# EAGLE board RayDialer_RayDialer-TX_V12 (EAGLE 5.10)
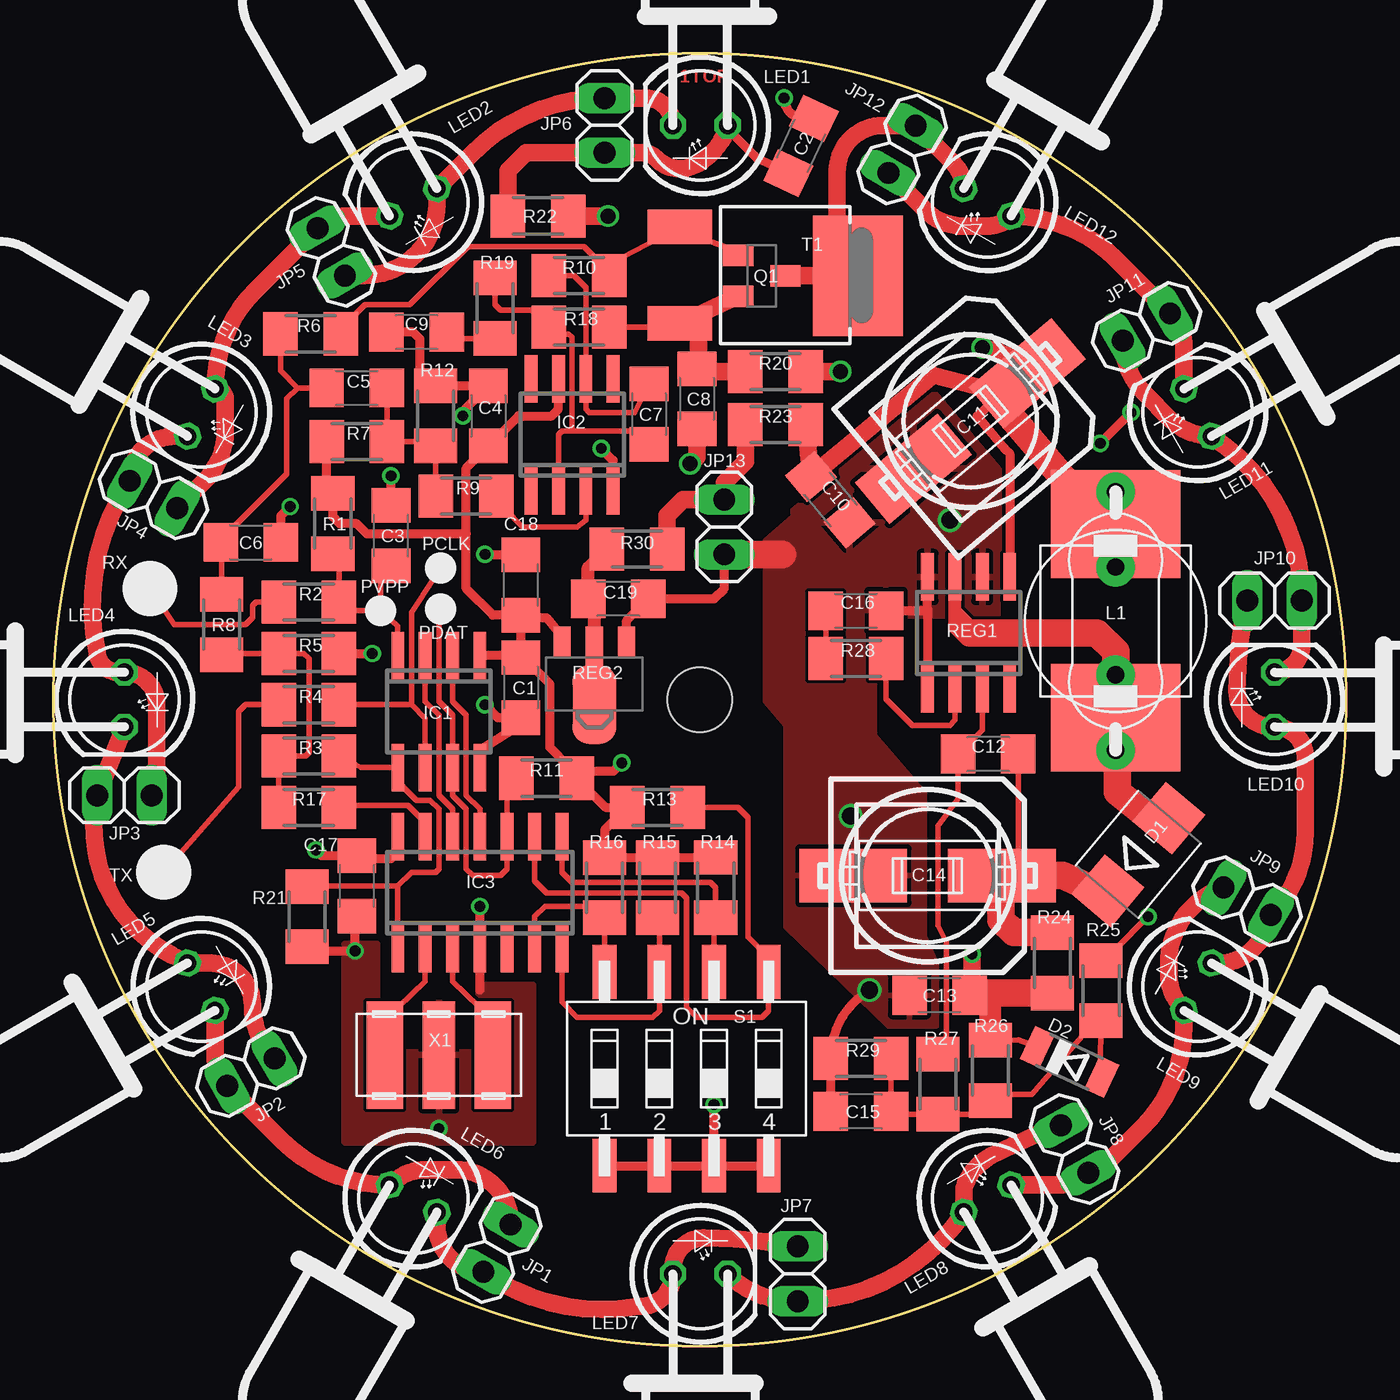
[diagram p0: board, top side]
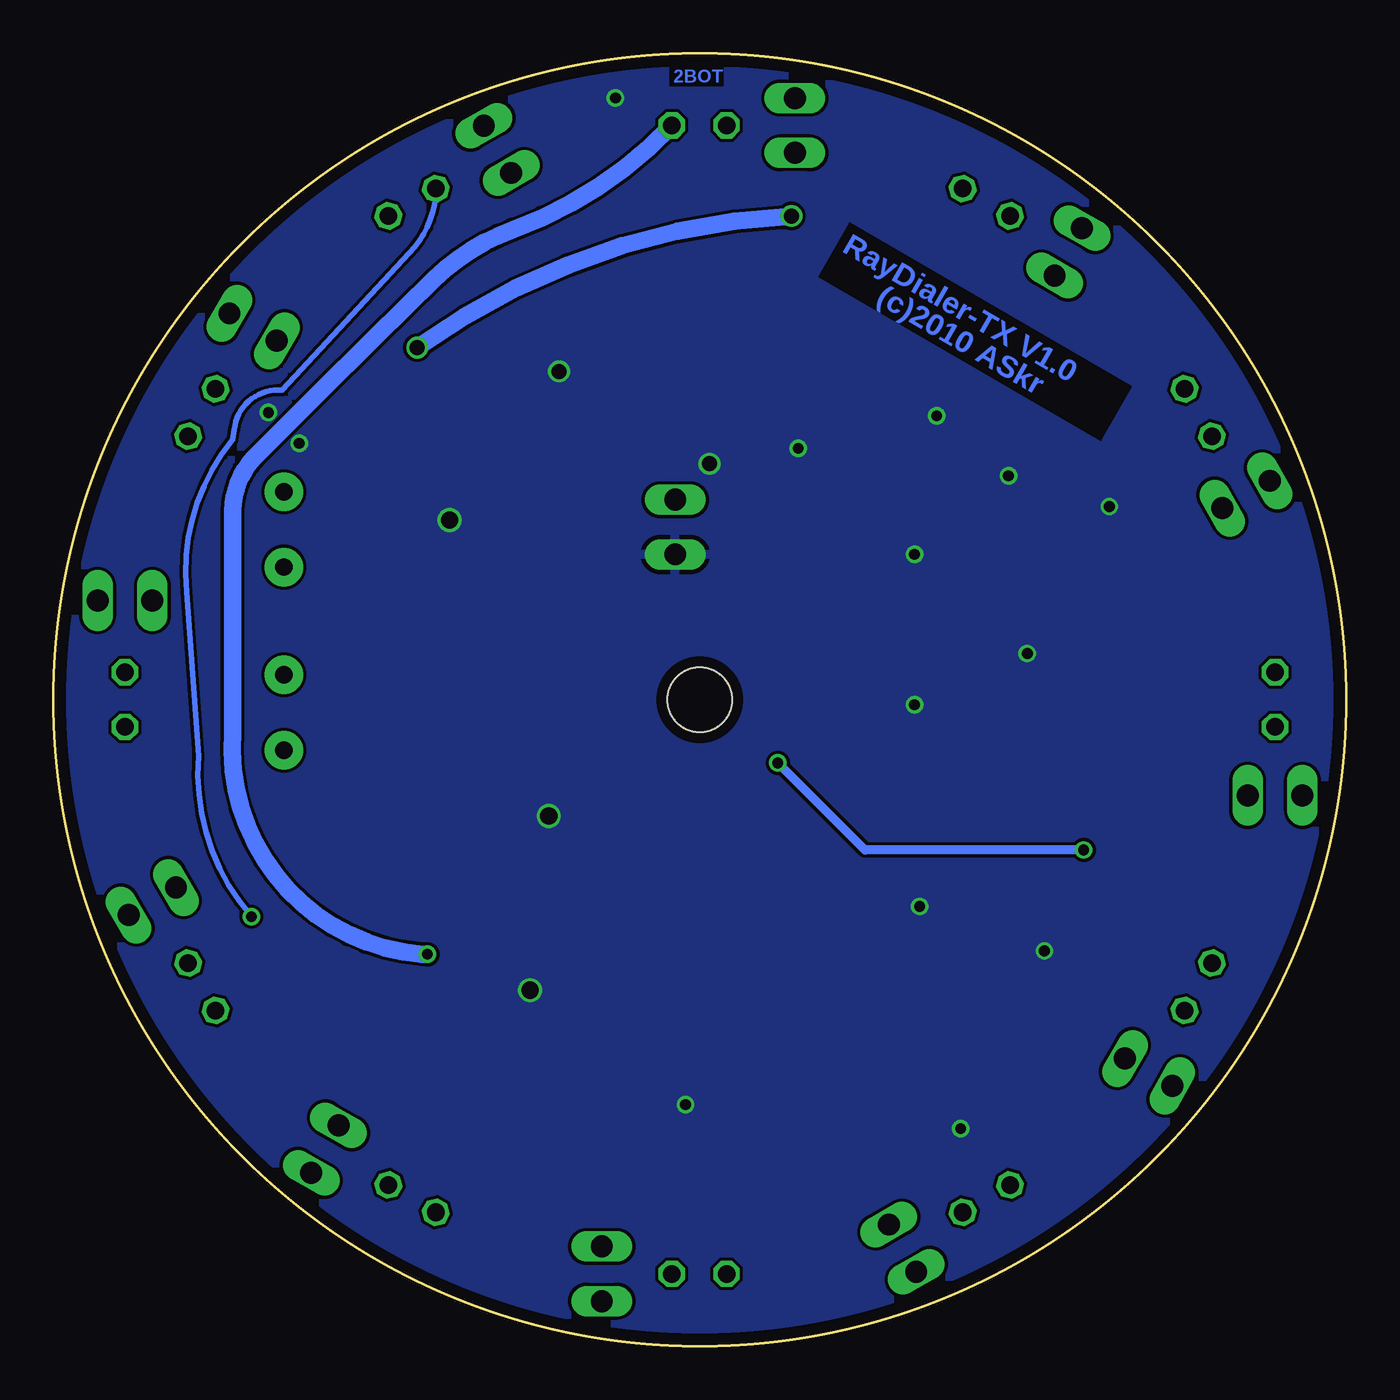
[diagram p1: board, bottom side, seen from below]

Size 60 x 60 mm. Coordinates in mm from the lower left corner, seen from the top.
Outline: circle at 30,30 radius 30
Copper layers (1*16): Top 0.035mm / dielectric 1.5mm / Bottom 0.035mm
Design rules "pcb-pool-2009": minimum track width 6mil, minimum drill 12mil, track to track 6mil, track to pad 6mil, pad to pad 6mil, via to via 6mil, smd to smd 6mil, copper to edge 20mil, drill to drill 8mil, minimum pad ring 8mil, minimum via ring 6mil, stop-mask expansion 3mil, vias tented up to drill 0mil, thermal gap 8mil
Holes 3 mm at 30,30
tRestrict: 6 lines
bRestrict: 8 lines

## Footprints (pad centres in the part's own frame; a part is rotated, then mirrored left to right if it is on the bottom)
C1206 = smd 1.6 x 1.8: 1 -1.4,0; 2 1.4,0
AKKI_CAP_MULTI2 = smd 5 x 2.5: + 3.45,0; - -3.45,0
AKKI_DIODE_SMB = smd 2.4 x 2.4: A 2.2,0; C -2.2,0
SOD80-R = smd 1 x 1.7: A 1.65,0; C -1.65,0
SOIC8 = smd 0.6 x 2.2: 1 -1.905,-2.6; 2 -0.635,-2.6; 3 0.635,-2.6; 4 1.905,-2.6; 5 1.905,2.6; 6 0.635,2.6; 7 -0.635,2.6; 8 -1.905,2.6
SO08 = smd 0.6 x 2.2: 1 -1.905,-2.6; 2 -0.635,-2.6; 3 0.635,-2.6; 4 1.905,-2.6; 5 1.905,2.6; 6 0.635,2.6; 7 -0.635,2.6; 8 -1.905,2.6
AKKI_SO-14 = smd 0.6 x 2.2: 1 -3.81,-2.6; 2 -2.54,-2.6; 3 -1.27,-2.6; 4 0,-2.6; 5 1.27,-2.6; 6 2.54,-2.6; 7 3.81,-2.6; 8 3.81,2.6; 9 2.54,2.6; 10 1.27,2.6; 11 0,2.6; 12 -1.27,2.6; 13 -2.54,2.6; 14 -3.81,2.6
1X02 = drill 1.016 long: 1 -1.27,0; 2 1.27,0
AKKI_MULTICOIL = drill 0.8 pad 1.778 round: 1@1 -6,0; 1@2 -2.5,0; 2@1 2.5,0; 2@2 6,0 | smd 5 x 6: 1@3 -4.5,0; 2@3 4.5,0
AKKI_LED5MM = drill 0.813 octagon: A -1.27,0; K 1.27,0
TP14R = smd 1.4 x 1.4: TP 0,0
SOT23-BEC = smd 1 x 1.4: B -0.95,-1.1; C 0,1.1; E 0.95,-1.1
M1206 = smd 1.6 x 2: 1 -1.4,0; 2 1.4,0
AKKI_SOIC8 = smd 0.6 x 2.2: 1 -1.905,-2.6; 2 -0.635,-2.6; 3 0.635,-2.6; 4 1.905,-2.6; 5 1.905,2.6; 6 0.635,2.6; 7 -0.635,2.6; 8 -1.905,2.6
SOT89 = smd 0.8 x 1.4: 1 -1.499,-1.981; 3 1.499,-1.981 | smd 0.8 x 1.9: 2 0,-1.727 | smd 2.032 x 3.65: 2@1 0,0.94
B2,54 = smd 2.54 x 2.54: TP 0,0
AKKI_SW04-SMD = smd 1.1 x 2.5: 1 -3.81,-4.5; 2 -1.27,-4.5; 3 1.27,-4.5; 4 3.81,-4.5; 5 3.81,4.5; 6 1.27,4.5; 7 -1.27,4.5; 8 -3.81,4.5
AKKI_DPAK = smd 1.6 x 2.997: 1 -2.261,-4.928; 3 2.21,-4.928 | smd 5.588 x 4.191: 4 0,3.353
AKKI_RESO3SMD = smd 1.7 x 5: 1 -2.5,0; 3 2.5,0 | smd 1.5 x 5: 2 0,0

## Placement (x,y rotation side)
C1  100n  [C1206]  21.69,30.56 270 top
C2  100n  [C1206]  34.71,55.72 65 top
C3  180p  [C1206]  15.66,37.63 90 top
C4  1u  [C1206]  20.18,43.18 270 top
C5  3n3  [C1206]  14.07,44.48 0 top
C6  330p  [C1206]  9.15,37.31 0 top
C7  180p  [C1206]  27.65,43.26 270 top
C8  33p  [C1206]  29.87,43.98 270 top
C9  10n  [C1206]  16.85,47.07 180 top
C10  100n  [C1206]  36.06,39.29 310 top
C11  150u;10V  [AKKI_CAP_MULTI2]  42.57,42.94 40 top
C12  n.p.  [C1206]  43.39,27.48 180 top
C13  1u;35V  [C1206]  41.14,16.27 180 top
C14  100u;35V  [AKKI_CAP_MULTI2]  40.58,21.83 0 top
C15  220n  [C1206]  37.49,10.88 180 top
C16  10u  [C1206]  37.25,34.13 0 top
C17  100n  [C1206]  14.07,21.35 270 top
C18  100n  [C1206]  21.69,35.32 90 top
C19  1u  [C1206]  26.22,34.69 180 top
D1  MBRS130  [AKKI_DIODE_SMB]  50.37,22.81 50 top
D2  30V  [SOD80-R]  47.17,13.18 335 top
IC1  PIC12F683  [SOIC8]  17.88,29.45 180 top
IC2  MCP601SN  [SO08]  24.07,42.31 0 top
IC3  HT9200  [AKKI_SO-14]  19.79,21.04 0 top
JP1  [1X02]  20.58,4.53 60 top
JP2  [1X02]  9.15,12.7 30 top
JP3  [1X02]  3.28,25.56 0 top
JP4  [1X02]  4.63,39.53 330 top
JP5  [1X02]  12.88,50.8 300 top
JP6  [1X02]  25.58,56.68 270 top
JP7  [1X02]  34.55,3.34 90 top
JP8  [1X02]  47.41,9.13 120 top
JP9  [1X02]  55.43,20.64 150 top
JP10  [1X02]  56.7,34.61 180 top
JP11  [1X02]  50.74,47.31 210 top
JP12  [1X02]  39.39,55.57 240 top
JP13  [1X02]  31.14,38.02 90 top
L1  100u  [AKKI_MULTICOIL]  49.31,33.66 270 top
LED1  [AKKI_LED5MM]  30.03,56.68 180 top
LED2  [AKKI_LED5MM]  16.69,53.1 210 top
LED3  [AKKI_LED5MM]  6.85,43.34 240 top
LED4  [AKKI_LED5MM]  3.28,30.01 270 top
LED5  [AKKI_LED5MM]  6.85,16.67 300 top
LED6  [AKKI_LED5MM]  16.69,6.83 330 top
LED7  [AKKI_LED5MM]  30.03,3.34 0 top
LED8  [AKKI_LED5MM]  43.36,6.83 30 top
LED9  [AKKI_LED5MM]  53.12,16.67 60 top
LED10  [AKKI_LED5MM]  56.7,30.01 90 top
LED11  [AKKI_LED5MM]  53.12,43.34 120 top
LED12  [AKKI_LED5MM]  43.36,53.1 150 top
PCLK  [TP14R]  17.96,36.12 0 top
PDAT  [TP14R]  17.96,34.21 0 top
PVPP  [TP14R]  15.18,34.13 0 top
Q1  BC817-40  [SOT23-BEC]  32.88,49.69 270 top
R1  100k  [M1206]  12.96,38.18 90 top
R2  1k  [M1206]  11.85,34.53 180 top
R3  100k  [M1206]  11.85,27.39 0 top
R4  1k  [M1206]  11.85,29.77 180 top
R5  47k  [M1206]  11.85,32.15 180 top
R6  n.p.  [M1206]  11.93,46.99 0 top
R7  470k  [M1206]  14.07,41.99 180 top
R8  100k  [M1206]  7.8,33.5 270 top
R9  47k  [M1206]  19.15,39.45 180 top
R10  1k  [M1206]  24.39,49.69 180 top
R11  100k  [M1206]  22.88,26.36 0 top
R12  82k  [M1206]  17.72,43.18 270 top
R13  100k  [M1206]  28.04,25.01 180 top
R14  100k  [M1206]  30.74,21.28 90 top
R15  100k  [M1206]  28.04,21.28 90 top
R16  100k  [M1206]  25.58,21.28 90 top
R17  0E  [M1206]  11.85,25.01 180 top
R18  100k  [M1206]  24.39,47.31 0 top
R19  100k  [M1206]  20.5,48.18 90 top
R20  10E  [M1206]  33.52,45.25 0 top
R21  100k  [M1206]  11.77,19.93 90 top
R22  0E; n.p.  [M1206]  22.49,52.47 180 top
R23  0E  [M1206]  33.52,42.79 0 top
R24  3E3  [M1206]  46.38,17.78 270 top
R25  82k  [M1206]  48.64,16.49 90 top
R26  n.p.  [M1206]  43.49,12.79 90 top
R27  1k  [M1206]  41.06,12.15 270 top
R28  4k7  [M1206]  37.25,31.91 0 top
R29  82k  [M1206]  37.49,13.34 0 top
R30  3E3  [M1206]  27.09,36.99 180 top
REG1  LT1172CS8  [AKKI_SOIC8]  42.49,33.1 0 top
REG2  S817A33  [SOT89]  25.11,30.72 180 top
RX  [B2,54]  4.47,35.17 0 top
S1  SW04-SMD  [AKKI_SW04-SMD]  29.39,12.86 0 top
T1  ZXT1053AK  [AKKI_DPAK]  34,49.69 270 top
TX  [B2,54]  5.1,21.99 0 top
X1  3.58MHz  [AKKI_RESO3SMD]  17.88,13.5 0 top

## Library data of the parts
C1-C3 C5-C10 C12 C15 C17 C18 R1-R30 = rcl
C4 C13 C16 C19 = rcl; TYPE: cer.
C11 C14 D1 D2 IC1 IC3 L1 LED1-LED12 REG1 REG2 S1 T1 X1 = Akki
IC2 = linear
JP1-JP13 = pinhead
PCLK PDAT PVPP RX TX = testpad
Q1 = transistor-npn

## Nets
+3V3: C1.1 C4.2 C17.1 C18.1 IC1.1 IC2.7 IC3.14 R1.2 R7.2 R11.2 R13.2 R14.2 R15.2 R16.2 REG2.3
+UB: JP13.2 R23.1 R30.1
GND: C1.2 C2.2 C3.2 C4.1 C6.2 C8.2 C9.2 C10.2 C11.- C13.2 C14.- C15.2 C16.2 C17.2 C18.2 C19.1 IC1.8 IC2.4 IC3.4 JP13.1 R5.1 R12.1 R20.2 R21.1 R29.1 REG1.1 REG1.6 REG1.8 REG2.1 S1.1 S1.2 S1.3 S1.4 X1.2
HT_CLK: IC1.2 IC3.11
HT_CS: IC1.5 IC3.1 R3.2 R21.2
HT_DAT: IC1.3 IC3.12
HT_SP: IC1.7 IC3.10 PDAT.TP R11.1
N$1: IC3.6 R16.1 S1.8
N$2: IC3.7 R15.1 S1.7
N$3: IC3.8 R14.1 S1.6
N$4: IC3.9 R13.1 S1.5
N$5: IC3.3 X1.3
N$6: IC3.2 X1.1
N$7: C5.2 R7.1 R9.2 R12.2
N$8: C15.1 D2.A R25.1 R26.1 R27.2 R29.2
N$9: IC2.3 R9.1
N$10: C7.1 IC2.6 R10.2
N$11: C5.1 C6.1 R6.1 R8.1
N$12: C8.1 Q1.E R18.2 R20.1 T1.3
N$13: C7.2 IC2.2 R18.1 R19.2
N$14: C9.1 R19.1
N$15: JP12.1 LED12.K Q1.C R25.2 T1.4
N$16: Q1.B R6.2 R10.1 T1.1
N$17: C19.2 R30.2 REG2.2
N$18: R3.1 R5.2 R8.2 R17.2
N$19: C10.1 C11.+ L1.1@1 R22.1 R23.2 REG1.5
N$20: R4.2 TX.TP
N$21: D1.A L1.2@2 REG1.7
N$22: IC3.13 R17.1
N$24: C12.1 C14.+ D1.C R24.1
N$25: R2.2 RX.TP
N$26: C16.1 R28.1
N$27: R28.2 REG1.2
N$28: C12.2 R27.1 REG1.3
N$29: JP5.2 JP6.1 LED1.K LED2.A
N$30: JP4.2 JP5.1 LED2.K LED3.A
N$31: JP3.2 JP4.1 LED3.K LED4.A
N$32: JP2.2 JP3.1 LED4.K LED5.A
N$33: JP1.2 JP2.1 LED5.K LED6.A
N$34: JP1.1 JP7.2 LED6.K LED7.A
N$35: JP7.1 JP8.2 LED7.K LED8.A
N$36: JP8.1 JP9.2 LED8.K LED9.A
N$37: JP9.1 JP10.2 LED9.K LED10.A
N$38: JP10.1 JP11.2 LED10.K LED11.A
N$39: JP11.1 JP12.2 LED11.K LED12.A
RX: C3.1 IC1.4 PVPP.TP R1.1 R2.1
TX: IC1.6 PCLK.TP R4.1
V+: C2.1 C13.1 D2.C JP6.2 LED1.A R22.2 R24.2 R26.2

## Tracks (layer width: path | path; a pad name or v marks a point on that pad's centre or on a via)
+3V3  (via drill 0.5)
  Top 0.406: IC1.1 21.44,32.05 C1.1 | IC3.14 15.98,22.94 15.66,22.62 14.2,22.62 C17.1 12.43,22.75 v12.17,23.02 | REG2.3 23.61,32.93 22.88,33.82 21.8,33.82 C18.1 | R15.2 R14.2 | R15.2 | R15.2 R16.2 25.58,23.95 R13.2 25.63,25.01 R11.2 | C1.1 21.8,31.96 23.04,30.72 23.04,27.78 23.91,26.91 23.91,26.72 R11.2 | IC2.7 23.44,43.5 23.12,43.18 21.58,43.18 C4.2 19.15,40.75 19.15,37.71 | C1.1 C18.1 | C1.1 | C18.1 20.39,33.92 19.15,35.17 19.15,37.71 | R7.2 12.67,39.87 R1.2 12.96,38.5 13.28,38.18 14.07,38.18 14.55,37.71 19.15,37.71 | v26.38,27.07 25.98,26.67 24.6,26.67 R11.2
  Bottom 0.406: v12.17,23.02 22.33,23.02 v26.38,27.07
+UB
  Top 0.813: R30.1 28.49,38.55 29.23,39.29 JP13.2 31.14,40.09 32.12,41.07 R23.1
GND  (via drill 0.5, 0.7, 0.8)
  Top 0.406: 40.58,34.21 REG1.1 | 40.58,34.21 REG1.8 | C16.2 40.5,34.13 40.58,34.21 | C17.2 13.99,19.88 v13.99,18.34 11.96,18.34 R21.1 | IC3.4 v19.79,20.4 | IC3.4 | IC3.4 19.79,16.51 | S1.1 S1.2 S1.3 | S1.3 S1.4 | S1.3 v30.66,11.19 | v30.66,11.19 | C19.1 30.66,34.69 31.14,35.17 JP13.1 | REG2.1 26.6,33.68 C19.1 | v20.03,29.77 20.63,29.16 C1.2 21.61,28.82 19.87,27.7 IC1.8 | C9.2 16.69,47.07 17.01,46.75 17.01,45.3 R12.1 C4.1 18.99,43.39 v18.99,43.18 | C6.2 10.55,38.55 v10.98,38.98 | R5.1 v14.79,32.15 | R5.1 | C18.2 20.05,36.72 v20.03,36.75 | C19.1 27.09,35.22 | C3.2 v15.66,40.4 | IC2.4 25.98,41.12 v25.42,41.67 | C15.2 R29.1 arc-59 v37.88,16.51 | C2.2 34.87,56.99 arc-90 v33.92,57.95 | v48.6,41.91 v50.03,43.34
  Top 0.813: R20.2 v36.54,45.25 | C8.2 29.87,41.28 v29.55,40.96
  Top 1.27: JP13.1 33.84,36.75
  other vias: 41.62,38.34 37.01,24.61 17.88,10.08
  pour Bottom: -1.56,61.52 61.3,61.52 61.3,-1.35 -1.56,-1.35
  pour Top: 34.31,38.74 40.9,44.21 43.92,40.64 43.92,34.05 39.87,34.05 39.87,36.36 36.3,36.36
  pour Top: 40.98,14.85 38.76,14.85 34,19.45 34,28.82 33.04,29.93 33.04,37.39 36.69,40.56 39.55,37.23 44.16,37.23 44.16,33.9 39.71,33.9 39.71,35.32 38.12,35.32 38.12,28.34 40.42,25.64 40.42,18.97 40.98,17.7
  pour Top: 13.52,18.66 15.03,18.66 15.03,16.75 22.25,16.75 22.25,9.45 13.52,9.45
HT_CLK
  Top 0.254: IC3.11 19.79,24.93 19.15,25.56 19.15,29.29 18.52,29.93 IC1.2
HT_CS
  Top 0.254: 15.98,21.35 IC3.1 | 15.98,21.35 16.61,21.99 17.72,21.99 17.88,22.15 17.88,24.93 17.49,25.32 16.85,25.32 15.98,26.2 IC1.5 14.26,26.85 R3.2 | 15.98,21.35 11.8,21.35 R21.2
HT_DAT
  Top 0.254: IC3.12 18.52,24.93 17.88,25.56 17.88,29.29 17.25,29.93 IC1.3
HT_SP
  Top 0.254: PDAT.TP 17.88,34.13 17.88,29.93 18.52,29.29 IC1.7 18.52,25.56 19.15,24.93 19.15,22.15 19.47,21.83 20.74,21.83 21.06,22.15 IC3.10 21.06,25.93 R11.1
N$1
  Top 0.254: R16.1 S1.8 | R16.1 | R16.1 25.55,19.87 25.03,20.4 22.8,20.4 22.33,19.93 IC3.6 | IC3.6
N$2
  Top 0.254: IC3.7 23.6,15.96 24.31,15.24 27.8,15.24 28.12,15.56 S1.7 28.12,19.88 R15.1 | IC3.7
N$3
  Top 0.254: S1.6 30.66,19.88 R14.1 30.74,21.28 30.5,21.51 24.07,21.51 23.6,21.99 IC3.8 | IC3.8
N$4
  Top 0.254: S1.5 33.2,15.56 32.88,15.24 29.87,15.24 29.39,15.72 29.39,20.8 29.15,21.04 22.88,21.04 22.33,21.59 IC3.9 | IC3.9 | R13.1 31.77,25.01 32.25,24.53 32.25,18.97 33.2,18.02 S1.5 | S1.5
N$5
  Top 0.254: X1.3 20.38,15.12 18.52,16.91 IC3.3
N$6
  Top 0.254: X1.1 15.38,15.12 17.25,16.91 IC3.2
N$7
  Top 0.254: R12.2 17.64,41.86 | R12.2 17.72,39.16 R9.2 | R12.2 | C5.2 R7.1 17.51,41.99 R12.2
N$8
  Top 0.254: R29.2 C15.1 39.02,10.75 R27.2 43.23,10.75 43.52,11.04 43.52,11.36 R26.1 43.77,11.67 45.43,11.67 47.77,14.39 R25.1 48.6,12.86 D2.A
N$9
  Top 0.254: R9.1 20.95,38.85 21.77,38.02 24.31,38.02 24.71,38.34 IC2.3 | IC2.3
N$10
  Top 0.254: R10.2 24.15,49.69 24.71,49.14 IC2.6 24.71,43.5 24.87,43.34 26.96,43.34 C7.1
N$11
  Top 0.254: R8.1 7.8,37.26 C6.1 7.75,37.42 10.82,40.48 10.82,43.98 11.33,44.48 | 11.33,44.48 C5.1 | 11.33,44.48 10.53,45.28 R6.1
N$12
  Top 0.254: R18.2 28.9,47.31 T1.3
  Top 0.813: 29.45,47.66 T1.3 | 29.45,47.66 Q1.E | C8.1 29.95,45.46 | 29.95,45.46 29.95,47.39 29.68,47.66 29.45,47.66 | 29.95,45.46 30.16,45.25 R20.1
N$13
  Top 0.254: 24.07,42.47 27.12,42.47 C7.2 | R19.2 20.5,48.34 20.74,48.1 22.2,48.1 R18.1 22.99,47.18 22.8,46.99 23.91,46.99 24.07,46.83 24.07,42.47 | IC2.2 23.44,42.31 23.6,42.47 24.07,42.47
N$14
  Top 0.254: R19.1 18.54,46.78 C9.1
N$15  (via drill 0.5)
  Top 0.254: 36.54,50.5 T1.4 | 36.38,54.53 arc108 36.54,55.17 | R25.2 49.27,18.38 v50.82,19.93
  Top 0.813: T1.4 Q1.C | LED12.K arc45 41.77,54.92 JP12.1 38.51,56.67 arc90 36.38,54.53 36.38,50.66 arc90 36.54,50.5
  Bottom 0.254: v50.82,19.93 arc45 53.28,27.38 53.84,35.01 arc45 51.69,42.07 51.62,42.55 arc90 49.39,44.37 43.5,50.74 arc-45 LED12.K
N$16
  Top 0.254: Q1.B 31.61,50.88 30.26,51.36 T1.1 29.03,51.99 28.44,51.99 28.44,51.83 27.96,51.36 25.98,50.33 25.88,50 | 25.88,50 R10.1 | R6.2 13.33,47.2 14.47,48.34 16.53,48.34 19.23,51.04 24.63,51.04 25.42,50.25 25.63,50.25 25.88,50
N$17
  Top 0.597: REG2.2 25.11,34.24 C19.2 24.82,36.12 R30.2
N$18
  Top 0.254: R3.1 | R17.2 | R17.2 R3.1 | R3.1 11.69,27.39 11.85,27.55 11.85,31.91 11.61,32.15 R5.2 | R5.2 | R5.2 7.85,32.15 R8.2
N$19  (via drill 0.7)
  Top 0.406: REG1.5 44.39,41.44 44.16,41.67 42.89,43.18 43.76,43.98 43.52,44.37
  Top 0.813: R23.2 C10.1 40.82,45.09 43.52,44.37 C11.+ arc45 v43.12,46.36 | R22.1 | v25.74,52.47 R22.1
  Top 1.27: L1.1@1 47.25,39.85 43.76,43.98
  Bottom 0.813: v43.12,46.36 arc33 v25.74,52.47
N$20
  Top 0.254: TX.TP 8.6,25.96 8.6,29.45 8.91,29.77 R4.2
N$21
  Top 0.597: 41.85,34.13 REG1.7 | 41.85,34.13 42.57,33.42 | 41.85,34.13 41.85,33.34 42.41,32.78 42.41,33.1 42.57,33.1
  Top 1.27: D1.A 51.46,24.05 49.39,25.72 49.39,26.75 L1.2@2 49.31,32.23 48.44,33.1 42.57,33.1
N$22
  Top 0.254: IC3.13 17.25,24.29 16.45,25.09 13.49,25.09 R17.1
N$24
  Top 0.254: C12.1 44.79,22.35 C14.+
  Top 1.27: D1.C 48.44,21.12 46.85,21.83 C14.+ 44,21.79 44,19.77 44.58,19.18 R24.1
N$25
  Top 0.254: R2.2 9.39,34.53 9.23,34.37 9.23,33.82 8.91,33.5 5.58,33.5 RX.TP
N$26
  Top 0.254: R28.1 C16.1
N$27
  Top 0.254: REG1.2 41.85,29.05 41.62,28.82 39.87,28.82 38.65,30.04 R28.2
N$28
  Top 0.254: REG1.3 43.12,28.61 C12.2 41.99,25.38 41.06,24.13 41.06,19.53 41.46,18.74 41.46,14.05 41.38,13.97 41.38,13.86 R27.1
N$29
  Top 0.813: JP5.2 14.39,49.7 arc45 16.85,50.72 arc45 17.79,53 LED2.A 19.46,55.41 arc-45 JP6.1 27.49,57.95 arc-90 LED1.K
N$30
  Top 0.813: LED2.K 13.62,52.47 arc45 JP5.1 9.39,49.05 arc45 LED3.A arc-90 7.96,43.97 7.96,42.47 arc-45 7.01,40.18 JP4.2
N$31
  Top 0.813: LED3.K 5.6,42.24 arc90 JP4.1 arc45 2.01,32.21 arc90 3.1,31.28 LED4.A arc-90 4.79,29.77 4.79,25.96 arc-62 JP3.2
N$32
  Top 0.813: LED4.K JP3.1 arc80 6.06,17.86 arc4 LED5.A 7.26,17.77 arc-90 9.23,15.8 arc45 JP2.2
N$33
  Top 0.813: LED5.K 7.48,13.44 arc45 JP2.1 10.58,9.54 arc45 LED6.A arc-45 17.32,8.18 18.66,8.18 arc-90 JP1.2
N$34
  Top 0.813: LED6.K 17.79,5.58 arc90 JP1.1 arc45 27.14,1.83 27.25,1.83 arc90 LED7.A 28.76,3.57 arc-90 30.19,5 arc-10 JP7.2
N$35
  Top 0.813: LED7.K arc45 34.36,2.07 JP7.1 arc56 LED8.A 42.26,7.31 arc-45 43.52,8.81 arc-8 JP8.2
N$36
  Top 0.813: LED8.K 46.68,7.46 arc45 JP8.1 arc45 48.74,8.32 50.51,10.08 arc45 52.49,14.87 LED9.A arc-45 51.78,17.3 51.78,17.7 arc-71 JP9.2
N$37
  Top 0.813: LED9.K 54.22,17.77 arc45 55.59,18.34 56.01,18.77 arc45 JP9.1 arc45 58.13,23.87 58.13,27.31 arc90 LED10.A 56.62,28.74 arc-90 54.95,30.4 arc-13 JP10.2
N$38
  Top 0.813: LED10.K arc90 57.97,32.55 JP10.1 arc58 LED11.A arc-45 51.84,43.04 50.66,44.22 arc-45 JP11.2
N$39
  Top 0.813: LED11.K 52.49,46.39 arc45 JP11.1 49.34,50.45 arc45 LED12.A arc-45 43.31,51.99 42.25,51.99 arc-45 40.51,52.72 JP12.2
RX
  Top 0.254: IC1.4 15.98,33.42 PVPP.TP | PVPP.TP 13.44,34.13 R2.1 13.25,36.41 R1.1 | PVPP.TP 15.18,35.83 C3.1
TX
  Top 0.254: IC1.6 17.25,29.13 16.61,29.77 | 16.61,29.77 16.61,34.05 PCLK.TP | 16.61,29.77 | R4.1 16.61,29.77
V+  (via drill 0.5)
  Top 0.254: R26.2 44.79,14.21 D2.C
  Top 0.406: C2.1 32.65,55.17 31.3,56.52 LED1.A
  Top 0.813: LED1.A arc-53 29.63,54.77 arc-67 28.04,55.09 arc45 27.28,55.41 JP6.2 21.93,55.41 21.09,54.56 R22.2 | 42.65,16.38 v42.65,18.18 | v42.65,18.18 arc-90 v42.65,18.18
  Top 1.016: R26.2 43.49,16.17 43.28,16.38
  Top 1.27: R24.2 43.28,16.38 42.65,16.38 C13.1
  Bottom 0.813: v42.65,18.18 42.89,18.18 arc90 51.7,28.5 51.7,38.79 arc45 50.51,41.44 arc1 42.33,49.53 arc24 38.68,51.83 arc-27 LED1.A

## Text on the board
Top: 1TOP
Bottom: 2BOT | RayDialer-TX V1.0 | (c)2010 ASkr
tDocu: V1.2 | layout | V1.0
